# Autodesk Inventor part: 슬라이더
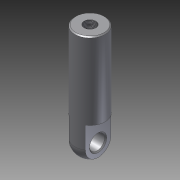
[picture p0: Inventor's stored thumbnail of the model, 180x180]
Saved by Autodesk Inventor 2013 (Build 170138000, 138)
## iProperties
Created: 2010-03
Part Number: 슬라이더
Document SubType Name: Modeling
Designer: Administrator
Density: 1 g/cm^3
Material: 강철, 연강
Author: Administrator
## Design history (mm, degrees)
sketch "스케치1"
  geometry: C1 r 14 at (0, 0); 1 further point
  constraints: 1 centre point, 1 coincident
  dimensions: "d2" = 28 diameter of C1
extrude "돌출1" new body sketch "스케치1" distance "d0" = 105; taper "d1" = 0 deg
chamfer "모따기1" distance "d3" = 1; stored, may be unused: second distance "d4" = 2, angle "d5" = 45 deg
sketch "스케치2"
  geometry: L1 (-7.5, 11.822)-(-7.5, -11.822); L2 (7.5, 11.822)-(7.5, -11.822); A1 r 14 centre (0, 0) between (-7.5, 11.822) and (7.5, 11.822) reference
  constraints: 4 end point, 4 point on circle, 2 vertical
  dimensions: "d6" = 15 distance between parallel lines of L2 L1; "d7" = 7.5 distance from line of A1.centre L2
extrude "돌출2" cut sketch "스케치2" distance "d8" = 34; taper "d9" = 0 deg
fillet "모깎기1" dims "d10" = 14
sketch "스케치3"
  geometry: C1 r 7 at (20, 11.822); A1 r 11.822 centre (20, 11.822) between (20, 0) and (20, 23.643) reference; 1 further point
  constraints: 1 centre point, 1 coincident
  dimensions: "d11" = 14 diameter of C1
extrude "돌출3" cut sketch "스케치3" stored distance "d12" = 25; taper "d13" = 0 deg
hole "구멍1" diameter "d16" = 10.917; stored, may be unused: countersink angle "d20" = 90 deg, drill point angle "d22" = 118 deg; dims "d14" = 10, "d15" = 10, "d17" = 15, "d18" = 4, "d19" = 2, "d21" = 20
chamfer "모따기2" distance "d23" = 1; stored, may be unused: second distance "d24" = 2, angle "d25" = 45 deg
node "솔리드1"
